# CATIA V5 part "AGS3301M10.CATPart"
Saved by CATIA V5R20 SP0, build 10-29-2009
Part number: AGS3301M10
Definition: NONE
Nomenclature: AGS3301M10
Source: Unknown
Description: AGS3301M10
Bounding box of the stored display mesh (mm): x -20 to 25, y -10.811 to 10.811, z -8.8 to 8.8
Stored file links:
  C:\Users\Utente\Desktop\IO LAVORO\3D X SITO CF\X SITO\PLASTICA\AGS\AGS3301M10.CATPart
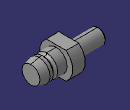
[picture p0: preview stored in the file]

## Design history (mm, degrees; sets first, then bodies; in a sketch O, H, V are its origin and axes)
Body1 "AGS3301M10" (main body)
  Solid1: solid without history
